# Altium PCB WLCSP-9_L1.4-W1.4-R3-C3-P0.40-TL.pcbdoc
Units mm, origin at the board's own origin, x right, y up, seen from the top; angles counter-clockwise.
Board outline 14.35 x 14.16 mm, 2 copper layers (Top Layer, Bottom Layer), stack 0 mm thick; 1 components, 0 nets, 9 pads, 0 vias.
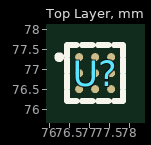
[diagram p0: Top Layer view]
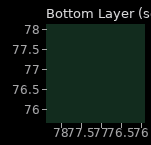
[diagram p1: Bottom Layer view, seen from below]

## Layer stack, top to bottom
Top Layer: signal copper (thickness not stored)
Bottom Layer: signal copper (thickness not stored)

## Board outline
84.197,69.85 69.85,69.85 69.85,84.01 84.197,84.01

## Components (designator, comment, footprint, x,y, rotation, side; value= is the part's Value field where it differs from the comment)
U? "" WLCSP-9_L1.4-W1.4-R3-C3-P0.40-TL 77.147,76.9 r0 top

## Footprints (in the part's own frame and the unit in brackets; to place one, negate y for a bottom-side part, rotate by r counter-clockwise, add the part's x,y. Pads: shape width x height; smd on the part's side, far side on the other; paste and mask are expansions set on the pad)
WLCSP-9_L1.4-W1.4-R3-C3-P0.40-TL [mm]
  round 0.2 smd: A1(-0.4,0.4) A2(0,0.4) A3(0.4,0.4) B1(-0.4,0) B2(0,0) B3(0.4,0) C1(-0.4,-0.4) C2(0,-0.4) C3(0.4,-0.4)
  silkscreen extent -0.95,-0.7 0.7,0.7

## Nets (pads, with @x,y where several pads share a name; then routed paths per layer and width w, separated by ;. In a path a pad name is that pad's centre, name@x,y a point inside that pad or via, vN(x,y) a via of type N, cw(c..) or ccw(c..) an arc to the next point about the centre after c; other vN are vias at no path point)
pads on no net: U?.A1 U?.A2 U?.A3 U?.B1 U?.B2 U?.B3 U?.C1 U?.C2 U?.C3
